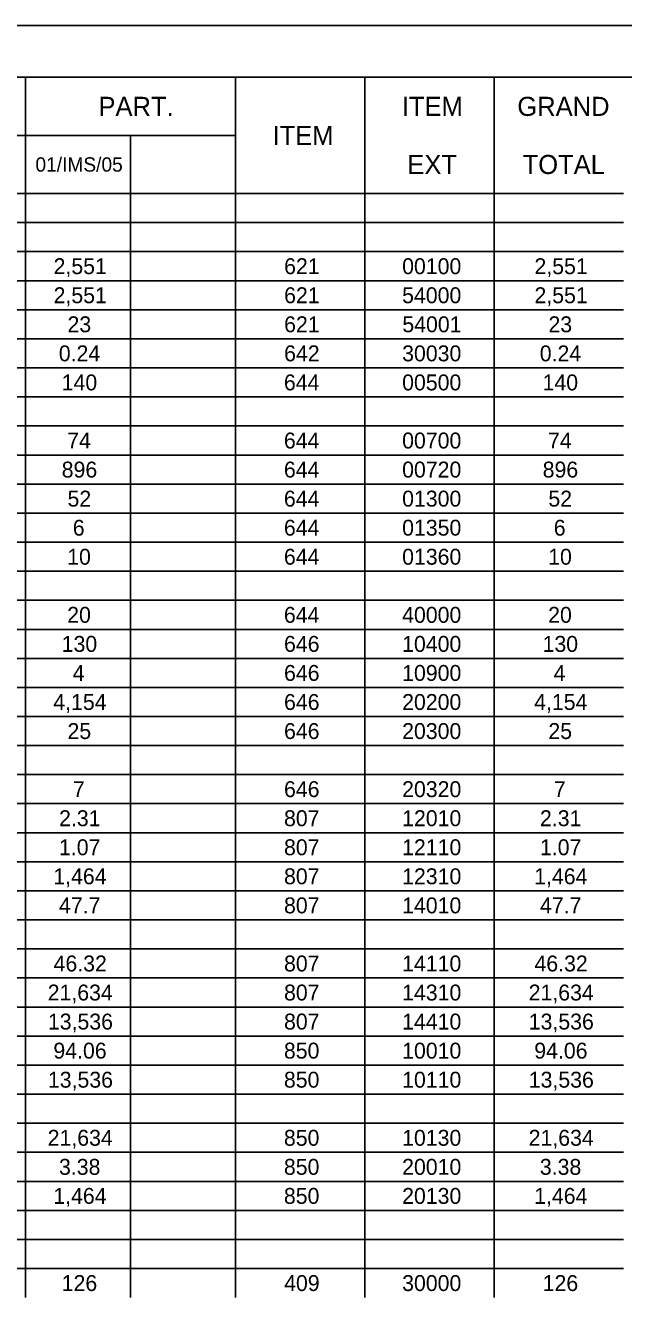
# Model space of a CAD drawing. Extents: x 0 to 34, y 0 to 22.
# Drawn here: x 9.6 to 15.36, y 9.74 to 22 of the extents above; entities that cross this region are included whole.
import ezdxf

# ---------------------------------------------------------------- set-up
doc = ezdxf.new("R2010")
doc.units = 0
for name, color, linetype in [('SH_Border', 7, 'Continuous'), ('SH_Cut_Line', 7, 'Continuous'), ('SH_Text', 7, 'Continuous')]:
    doc.layers.add(name, color=color, linetype=linetype)

msp = doc.modelspace()

# ---------------------------------------------------------------- linework, layer by layer
at = {"layer": 'SH_Border'}
msp.add_lwpolyline([(1.5, 21.5), (33.5, 21.5), (33.5, 0.5), (1.5, 0.5)], close=True, dxfattribs=at)
at = {"layer": 'SH_Cut_Line'}
msp.add_lwpolyline([(0, 0), (34, 0), (34, 22), (0, 22)], close=True, dxfattribs=at)
at = {"layer": 'SH_Text'}
for p, q in [((8.586, 21.5), (9.599, 21.5)), ((9.599, 21.5), (11.623, 21.5)), ((9.599, 21.5), (9.599, 21.22)), ((11.623, 21.5), (12.869, 21.5)), ((11.623, 21.5), (11.623, 21.22)), ((12.869, 21.5), (14.115, 21.5)), ((12.869, 21.5), (12.869, 21.22)), ((14.115, 21.5), (15.361, 21.5)), ((14.115, 21.5), (14.115, 21.22)), ((9.599, 21.22), (9.599, 20.94)), ((11.623, 21.22), (11.623, 20.94)), ((12.869, 21.22), (12.869, 20.94)), ((14.115, 21.22), (14.115, 20.94)), ((8.586, 20.94), (9.599, 20.94)), ((9.599, 20.94), (11.623, 20.94)), ((9.599, 20.94), (9.599, 20.66)), ((10.611, 20.94), (10.611, 20.66)), ((11.623, 20.94), (11.623, 20.66)), ((12.869, 20.94), (12.869, 20.66)), ((14.115, 20.94), (14.115, 20.66)), ((9.599, 20.66), (9.599, 20.38)), ((10.611, 20.66), (10.611, 20.38)), ((11.623, 20.66), (11.623, 20.38)), ((12.869, 20.66), (12.869, 20.38)), ((14.115, 20.66), (14.115, 20.38)), ((8.586, 20.38), (9.599, 20.38)), ((9.599, 20.38), (11.623, 20.38)), ((9.599, 20.38), (9.599, 20.1)), ((10.611, 20.38), (10.611, 20.1)), ((11.623, 20.38), (12.869, 20.38)), ((11.623, 20.38), (11.623, 20.1)), ((12.869, 20.38), (14.115, 20.38)), ((12.869, 20.38), (12.869, 20.1)), ((14.115, 20.38), (15.361, 20.38)), ((14.115, 20.38), (14.115, 20.1)), ((8.586, 20.1), (9.599, 20.1)), ((9.599, 20.1), (11.623, 20.1)), ((9.599, 20.1), (9.599, 18.7)), ((10.611, 20.1), (10.611, 18.7)), ((11.623, 20.1), (12.869, 20.1)), ((11.623, 20.1), (11.623, 18.7)), ((12.869, 20.1), (14.115, 20.1)), ((12.869, 20.1), (12.869, 18.7)), ((14.115, 20.1), (15.361, 20.1)), ((14.115, 20.1), (14.115, 18.7)), ((8.586, 19.82), (9.599, 19.82)), ((9.599, 19.82), (11.623, 19.82)), ((11.623, 19.82), (12.869, 19.82)), ((12.869, 19.82), (14.115, 19.82)), ((14.115, 19.82), (15.361, 19.82)), ((8.586, 19.54), (9.599, 19.54)), ((9.599, 19.54), (11.623, 19.54)), ((11.623, 19.54), (12.869, 19.54)), ((12.869, 19.54), (14.115, 19.54)), ((14.115, 19.54), (15.361, 19.54)), ((8.586, 19.26), (9.599, 19.26)), ((9.599, 19.26), (11.623, 19.26)), ((11.623, 19.26), (12.869, 19.26)), ((12.869, 19.26), (14.115, 19.26)), ((14.115, 19.26), (15.361, 19.26)), ((8.586, 18.98), (9.599, 18.98)), ((9.599, 18.98), (11.623, 18.98)), ((11.623, 18.98), (12.869, 18.98)), ((12.869, 18.98), (14.115, 18.98)), ((14.115, 18.98), (15.361, 18.98)), ((8.586, 18.7), (9.599, 18.7)), ((9.599, 18.7), (11.623, 18.7)), ((9.599, 18.7), (9.599, 18.14)), ((10.611, 18.7), (10.611, 18.14)), ((11.623, 18.7), (12.869, 18.7)), ((11.623, 18.7), (11.623, 18.14)), ((12.869, 18.7), (14.115, 18.7)), ((12.869, 18.7), (12.869, 18.14)), ((14.115, 18.7), (15.361, 18.7)), ((14.115, 18.7), (14.115, 18.14)), ((8.586, 18.42), (9.599, 18.42)), ((9.599, 18.42), (11.623, 18.42)), ((11.623, 18.42), (12.869, 18.42)), ((12.869, 18.42), (14.115, 18.42)), ((14.115, 18.42), (15.361, 18.42)), ((8.586, 18.14), (9.599, 18.14)), ((9.599, 18.14), (11.623, 18.14)), ((9.599, 18.14), (9.599, 17.86)), ((10.611, 18.14), (10.611, 17.86)), ((11.623, 18.14), (12.869, 18.14)), ((11.623, 18.14), (11.623, 17.86)), ((12.869, 18.14), (14.115, 18.14)), ((12.869, 18.14), (12.869, 17.86)), ((14.115, 18.14), (15.361, 18.14)), ((14.115, 18.14), (14.115, 17.86)), ((8.586, 17.86), (9.599, 17.86)), ((9.599, 17.86), (11.623, 17.86)), ((9.599, 17.86), (9.599, 17.58)), ((10.611, 17.86), (10.611, 17.58)), ((11.623, 17.86), (12.869, 17.86)), ((11.623, 17.86), (11.623, 17.58)), ((12.869, 17.86), (14.115, 17.86)), ((12.869, 17.86), (12.869, 17.58)), ((14.115, 17.86), (15.361, 17.86)), ((14.115, 17.86), (14.115, 17.58)), ((8.586, 17.58), (9.599, 17.58)), ((9.599, 17.58), (11.623, 17.58)), ((9.599, 17.58), (9.599, 17.3)), ((10.611, 17.58), (10.611, 17.3)), ((11.623, 17.58), (12.869, 17.58)), ((11.623, 17.58), (11.623, 17.3)), ((12.869, 17.58), (14.115, 17.58)), ((12.869, 17.58), (12.869, 17.3)), ((14.115, 17.58), (15.361, 17.58)), ((14.115, 17.58), (14.115, 17.3)), ((8.586, 17.3), (9.599, 17.3)), ((9.599, 17.3), (11.623, 17.3)), ((9.599, 17.3), (9.599, 17.02)), ((10.611, 17.3), (10.611, 17.02)), ((11.623, 17.3), (12.869, 17.3)), ((11.623, 17.3), (11.623, 17.02)), ((12.869, 17.3), (14.115, 17.3)), ((12.869, 17.3), (12.869, 17.02)), ((14.115, 17.3), (15.361, 17.3)), ((14.115, 17.3), (14.115, 17.02)), ((8.586, 17.02), (9.599, 17.02)), ((9.599, 17.02), (11.623, 17.02)), ((9.599, 17.02), (9.599, 16.74)), ((10.611, 17.02), (10.611, 16.74)), ((11.623, 17.02), (12.869, 17.02)), ((11.623, 17.02), (11.623, 16.74)), ((12.869, 17.02), (14.115, 17.02)), ((12.869, 17.02), (12.869, 16.74)), ((14.115, 17.02), (15.361, 17.02)), ((14.115, 17.02), (14.115, 16.74)), ((8.586, 16.74), (9.599, 16.74)), ((9.599, 16.74), (11.623, 16.74)), ((9.599, 16.74), (9.599, 16.18)), ((10.611, 16.74), (10.611, 16.18)), ((11.623, 16.74), (12.869, 16.74)), ((11.623, 16.74), (11.623, 16.18)), ((12.869, 16.74), (14.115, 16.74)), ((12.869, 16.74), (12.869, 16.18)), ((14.115, 16.74), (15.361, 16.74)), ((14.115, 16.74), (14.115, 16.18)), ((8.586, 16.46), (9.599, 16.46)), ((9.599, 16.46), (11.623, 16.46)), ((11.623, 16.46), (12.869, 16.46)), ((12.869, 16.46), (14.115, 16.46)), ((14.115, 16.46), (15.361, 16.46)), ((8.586, 16.18), (9.599, 16.18)), ((9.599, 16.18), (11.623, 16.18)), ((9.599, 16.18), (9.599, 15.9)), ((10.611, 16.18), (10.611, 15.9)), ((11.623, 16.18), (12.869, 16.18)), ((11.623, 16.18), (11.623, 15.9)), ((12.869, 16.18), (14.115, 16.18)), ((12.869, 16.18), (12.869, 15.9)), ((14.115, 16.18), (15.361, 16.18)), ((14.115, 16.18), (14.115, 15.9)), ((8.586, 15.9), (9.599, 15.9)), ((9.599, 15.9), (11.623, 15.9)), ((9.599, 15.9), (9.599, 15.62)), ((10.611, 15.9), (10.611, 15.62)), ((11.623, 15.9), (12.869, 15.9)), ((11.623, 15.9), (11.623, 15.62)), ((12.869, 15.9), (14.115, 15.9)), ((12.869, 15.9), (12.869, 15.62)), ((14.115, 15.9), (15.361, 15.9)), ((14.115, 15.9), (14.115, 15.62)), ((8.586, 15.62), (9.599, 15.62)), ((9.599, 15.62), (11.623, 15.62)), ((9.599, 15.62), (9.599, 15.34)), ((10.611, 15.62), (10.611, 15.34)), ((11.623, 15.62), (12.869, 15.62)), ((11.623, 15.62), (11.623, 15.34)), ((12.869, 15.62), (14.115, 15.62)), ((12.869, 15.62), (12.869, 15.34)), ((14.115, 15.62), (15.361, 15.62)), ((14.115, 15.62), (14.115, 15.34)), ((8.586, 15.34), (9.599, 15.34)), ((9.599, 15.34), (11.623, 15.34)), ((9.599, 15.34), (9.599, 14.78)), ((10.611, 15.34), (10.611, 14.78)), ((11.623, 15.34), (12.869, 15.34)), ((11.623, 15.34), (11.623, 14.78)), ((12.869, 15.34), (14.115, 15.34)), ((12.869, 15.34), (12.869, 14.78)), ((14.115, 15.34), (15.361, 15.34)), ((14.115, 15.34), (14.115, 14.78)), ((8.586, 15.06), (9.599, 15.06)), ((9.599, 15.06), (11.623, 15.06)), ((11.623, 15.06), (12.869, 15.06)), ((12.869, 15.06), (14.115, 15.06)), ((14.115, 15.06), (15.361, 15.06)), ((8.586, 14.78), (9.599, 14.78)), ((9.599, 14.78), (11.623, 14.78)), ((9.599, 14.78), (9.599, 14.5)), ((10.611, 14.78), (10.611, 14.5)), ((11.623, 14.78), (12.869, 14.78)), ((11.623, 14.78), (11.623, 14.5)), ((12.869, 14.78), (14.115, 14.78)), ((12.869, 14.78), (12.869, 14.5)), ((14.115, 14.78), (15.361, 14.78)), ((14.115, 14.78), (14.115, 14.5)), ((8.586, 14.5), (9.599, 14.5)), ((9.599, 14.5), (11.623, 14.5)), ((9.599, 14.5), (9.599, 14.22)), ((10.611, 14.5), (10.611, 14.22)), ((11.623, 14.5), (12.869, 14.5)), ((11.623, 14.5), (11.623, 14.22)), ((12.869, 14.5), (14.115, 14.5)), ((12.869, 14.5), (12.869, 14.22)), ((14.115, 14.5), (15.361, 14.5)), ((14.115, 14.5), (14.115, 14.22)), ((8.586, 14.22), (9.599, 14.22)), ((9.599, 14.22), (11.623, 14.22)), ((9.599, 14.22), (9.599, 13.94)), ((10.611, 14.22), (10.611, 13.94)), ((11.623, 14.22), (12.869, 14.22)), ((11.623, 14.22), (11.623, 13.94)), ((12.869, 14.22), (14.115, 14.22)), ((12.869, 14.22), (12.869, 13.94)), ((14.115, 14.22), (15.361, 14.22)), ((14.115, 14.22), (14.115, 13.94)), ((8.586, 13.94), (9.599, 13.94)), ((9.599, 13.94), (11.623, 13.94)), ((9.599, 13.94), (9.599, 11.7)), ((10.611, 13.94), (10.611, 11.7)), ((11.623, 13.94), (12.869, 13.94)), ((11.623, 13.94), (11.623, 11.7)), ((12.869, 13.94), (14.115, 13.94)), ((12.869, 13.94), (12.869, 11.7)), ((14.115, 13.94), (15.361, 13.94)), ((14.115, 13.94), (14.115, 11.7)), ((8.586, 13.66), (9.599, 13.66)), ((9.599, 13.66), (11.623, 13.66)), ((11.623, 13.66), (12.869, 13.66)), ((12.869, 13.66), (14.115, 13.66)), ((14.115, 13.66), (15.361, 13.66)), ((8.586, 13.38), (9.599, 13.38)), ((9.599, 13.38), (11.623, 13.38)), ((11.623, 13.38), (12.869, 13.38)), ((12.869, 13.38), (14.115, 13.38)), ((14.115, 13.38), (15.361, 13.38)), ((8.586, 13.1), (9.599, 13.1)), ((9.599, 13.1), (11.623, 13.1)), ((11.623, 13.1), (12.869, 13.1)), ((12.869, 13.1), (14.115, 13.1)), ((14.115, 13.1), (15.361, 13.1)), ((8.586, 12.82), (9.599, 12.82)), ((9.599, 12.82), (11.623, 12.82)), ((11.623, 12.82), (12.869, 12.82)), ((12.869, 12.82), (14.115, 12.82)), ((14.115, 12.82), (15.361, 12.82)), ((8.586, 12.54), (9.599, 12.54)), ((9.599, 12.54), (11.623, 12.54)), ((11.623, 12.54), (12.869, 12.54)), ((12.869, 12.54), (14.115, 12.54)), ((14.115, 12.54), (15.361, 12.54)), ((8.586, 12.26), (9.599, 12.26)), ((9.599, 12.26), (11.623, 12.26)), ((11.623, 12.26), (12.869, 12.26)), ((12.869, 12.26), (14.115, 12.26)), ((14.115, 12.26), (15.361, 12.26)), ((8.586, 11.98), (9.599, 11.98)), ((9.599, 11.98), (11.623, 11.98)), ((11.623, 11.98), (12.869, 11.98)), ((12.869, 11.98), (14.115, 11.98)), ((14.115, 11.98), (15.361, 11.98)), ((8.586, 11.7), (9.599, 11.7)), ((9.599, 11.7), (11.623, 11.7)), ((9.599, 11.7), (9.599, 11.42)), ((10.611, 11.7), (10.611, 11.42)), ((11.623, 11.7), (12.869, 11.7)), ((11.623, 11.7), (11.623, 11.42)), ((12.869, 11.7), (14.115, 11.7)), ((12.869, 11.7), (12.869, 11.42)), ((14.115, 11.7), (15.361, 11.7)), ((14.115, 11.7), (14.115, 11.42)), ((8.586, 11.42), (9.599, 11.42)), ((9.599, 11.42), (11.623, 11.42)), ((9.599, 11.42), (9.599, 10.3)), ((10.611, 11.42), (10.611, 10.3)), ((11.623, 11.42), (12.869, 11.42)), ((11.623, 11.42), (11.623, 10.3)), ((12.869, 11.42), (14.115, 11.42)), ((12.869, 11.42), (12.869, 10.3)), ((14.115, 11.42), (15.361, 11.42)), ((14.115, 11.42), (14.115, 10.3)), ((8.586, 11.14), (9.599, 11.14)), ((9.599, 11.14), (11.623, 11.14)), ((11.623, 11.14), (12.869, 11.14)), ((12.869, 11.14), (14.115, 11.14)), ((14.115, 11.14), (15.361, 11.14)), ((8.586, 10.86), (9.599, 10.86)), ((9.599, 10.86), (11.623, 10.86)), ((11.623, 10.86), (12.869, 10.86)), ((12.869, 10.86), (14.115, 10.86)), ((14.115, 10.86), (15.361, 10.86)), ((8.586, 10.58), (9.599, 10.58)), ((9.599, 10.58), (11.623, 10.58)), ((11.623, 10.58), (12.869, 10.58)), ((12.869, 10.58), (14.115, 10.58)), ((14.115, 10.58), (15.361, 10.58)), ((8.586, 10.3), (9.599, 10.3)), ((9.599, 10.3), (11.623, 10.3)), ((9.599, 10.3), (9.599, 10.02)), ((10.611, 10.3), (10.611, 10.02)), ((11.623, 10.3), (12.869, 10.3)), ((11.623, 10.3), (11.623, 10.02)), ((12.869, 10.3), (14.115, 10.3)), ((12.869, 10.3), (12.869, 10.02)), ((14.115, 10.3), (15.361, 10.3)), ((14.115, 10.3), (14.115, 10.02)), ((8.586, 10.02), (9.599, 10.02)), ((9.599, 10.02), (11.623, 10.02)), ((9.599, 10.02), (9.599, 9.74)), ((10.611, 10.02), (10.611, 9.74)), ((11.623, 10.02), (12.869, 10.02)), ((11.623, 10.02), (11.623, 9.74)), ((12.869, 10.02), (14.115, 10.02)), ((12.869, 10.02), (12.869, 9.74)), ((14.115, 10.02), (15.361, 10.02)), ((14.115, 10.02), (14.115, 9.74))]:
    msp.add_line(p, q, dxfattribs=at)

# ---------------------------------------------------------------- texts
for s, height, p in [('PART.', 0.184, (10.302, 21.128)), ('ITEM', 0.184, (13.225, 21.128)), ('GRAND', 0.184, (14.338, 21.128)), ('ITEM', 0.184, (11.979, 20.848)), ('01/IMS/05', 0.138, (9.695, 20.591)), ('EXT', 0.184, (13.278, 20.568)), ('TOTAL', 0.184, (14.389, 20.568)), ('2,551', 0.1533, (9.87, 19.603)), ('621', 0.1533, (12.091, 19.603)), ('00100', 0.1533, (13.228, 19.603)), ('2,551', 0.1533, (14.503, 19.603)), ('2,551', 0.1533, (9.87, 19.323)), ('621', 0.1533, (12.091, 19.323)), ('54000', 0.1533, (13.228, 19.323)), ('2,551', 0.1533, (14.503, 19.323)), ('23', 0.1533, (10.004, 19.043)), ('621', 0.1533, (12.091, 19.043)), ('54001', 0.1533, (13.23, 19.043)), ('23', 0.1533, (14.638, 19.043)), ('0.24', 0.1533, (9.92, 18.763)), ('642', 0.1533, (12.091, 18.763)), ('30030', 0.1533, (13.228, 18.763)), ('0.24', 0.1533, (14.554, 18.763)), ('140', 0.1533, (9.948, 18.483)), ('644', 0.1533, (12.089, 18.483)), ('00500', 0.1533, (13.228, 18.483)), ('140', 0.1533, (14.581, 18.483)), ('74', 0.1533, (10.001, 17.923)), ('644', 0.1533, (12.089, 17.923)), ('00700', 0.1533, (13.228, 17.923)), ('74', 0.1533, (14.634, 17.923)), ('896', 0.1533, (9.948, 17.643)), ('644', 0.1533, (12.089, 17.643)), ('00720', 0.1533, (13.228, 17.643)), ('896', 0.1533, (14.582, 17.643)), ('52', 0.1533, (10.004, 17.363)), ('644', 0.1533, (12.089, 17.363)), ('01300', 0.1533, (13.228, 17.363)), ('52', 0.1533, (14.637, 17.363)), ('6', 0.153, (10.055, 17.083)), ('644', 0.1533, (12.089, 17.083)), ('01350', 0.1533, (13.228, 17.083)), ('6', 0.153, (14.689, 17.083)), ('10', 0.1533, (10.001, 16.803)), ('644', 0.1533, (12.089, 16.803)), ('01360', 0.1533, (13.228, 16.803)), ('10', 0.1533, (14.635, 16.803)), ('20', 0.1533, (10.001, 16.243)), ('644', 0.1533, (12.089, 16.243)), ('40000', 0.1533, (13.228, 16.243)), ('20', 0.1533, (14.635, 16.243)), ('130', 0.1533, (9.948, 15.963)), ('646', 0.1533, (12.09, 15.963)), ('10400', 0.1533, (13.228, 15.963)), ('130', 0.1533, (14.581, 15.963)), ('4', 0.153, (10.054, 15.683)), ('646', 0.1533, (12.09, 15.683)), ('10900', 0.1533, (13.228, 15.683)), ('4', 0.153, (14.688, 15.683)), ('4,154', 0.1533, (9.867, 15.403)), ('646', 0.1533, (12.09, 15.403)), ('20200', 0.1533, (13.228, 15.403)), ('4,154', 0.1533, (14.5, 15.403)), ('25', 0.1533, (10.004, 15.123)), ('646', 0.1533, (12.09, 15.123)), ('20300', 0.1533, (13.228, 15.123)), ('25', 0.1533, (14.637, 15.123)), ('7', 0.153, (10.056, 14.563)), ('646', 0.1533, (12.09, 14.563)), ('20320', 0.1533, (13.228, 14.563)), ('7', 0.153, (14.69, 14.563)), ('2.31', 0.1533, (9.923, 14.283)), ('807', 0.1533, (12.09, 14.283)), ('12010', 0.1533, (13.228, 14.283)), ('2.31', 0.1533, (14.556, 14.283)), ('1.07', 0.1533, (9.922, 14.003)), ('807', 0.1533, (12.09, 14.003)), ('12110', 0.1533, (13.228, 14.003)), ('1.07', 0.1533, (14.556, 14.003)), ('1,464', 0.1533, (9.867, 13.723)), ('807', 0.1533, (12.09, 13.723)), ('12310', 0.1533, (13.228, 13.723)), ('1,464', 0.1533, (14.5, 13.723)), ('47.7', 0.1533, (9.922, 13.443)), ('807', 0.1533, (12.09, 13.443)), ('14010', 0.1533, (13.228, 13.443)), ('47.7', 0.1533, (14.556, 13.443)), ('46.32', 0.1533, (9.87, 12.883)), ('807', 0.1533, (12.09, 12.883)), ('14110', 0.1533, (13.228, 12.883)), ('46.32', 0.1533, (14.503, 12.883)), ('21,634', 0.1533, (9.813, 12.603)), ('807', 0.1533, (12.09, 12.603)), ('14310', 0.1533, (13.228, 12.603)), ('21,634', 0.1533, (14.447, 12.603)), ('13,536', 0.1533, (9.815, 12.323)), ('807', 0.1533, (12.09, 12.323)), ('14410', 0.1533, (13.228, 12.323)), ('13,536', 0.1533, (14.448, 12.323)), ('94.06', 0.1533, (9.868, 12.043)), ('850', 0.1533, (12.089, 12.043)), ('10010', 0.1533, (13.228, 12.043)), ('94.06', 0.1533, (14.501, 12.043)), ('13,536', 0.1533, (9.815, 11.763)), ('850', 0.1533, (12.089, 11.763)), ('10110', 0.1533, (13.228, 11.763)), ('13,536', 0.1533, (14.448, 11.763)), ('21,634', 0.1533, (9.813, 11.203)), ('850', 0.1533, (12.089, 11.203)), ('10130', 0.1533, (13.228, 11.203)), ('21,634', 0.1533, (14.447, 11.203)), ('3.38', 0.1533, (9.922, 10.923)), ('850', 0.1533, (12.089, 10.923)), ('20010', 0.1533, (13.228, 10.923)), ('3.38', 0.1533, (14.555, 10.923)), ('1,464', 0.1533, (9.867, 10.643)), ('850', 0.1533, (12.089, 10.643)), ('20130', 0.1533, (13.228, 10.643)), ('1,464', 0.1533, (14.5, 10.643)), ('126', 0.1533, (9.948, 9.803)), ('409', 0.1533, (12.091, 9.803)), ('30000', 0.1533, (13.228, 9.803)), ('126', 0.1533, (14.582, 9.803))]:
    msp.add_text(s, height=height, dxfattribs=at).set_placement(p)

doc.saveas('drawing.dxf')
